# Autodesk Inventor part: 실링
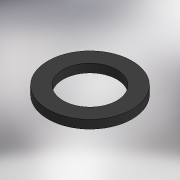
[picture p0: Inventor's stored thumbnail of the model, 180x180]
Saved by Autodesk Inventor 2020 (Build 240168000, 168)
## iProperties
Created: 2024-11
Part Number: 실링
Material: 고무
Document SubType Name: Modeling
Designer: 1강의실14
Density: 0.93 g/cm^3
Appearance: 기본값
Author: jhkim
Sending System: Autodesk Inventor 2025
Preprocessor: ST-DEVELOPER v20
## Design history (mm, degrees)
feature "솔리드1"
node "솔리드2"
